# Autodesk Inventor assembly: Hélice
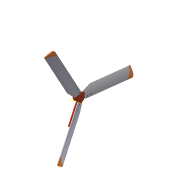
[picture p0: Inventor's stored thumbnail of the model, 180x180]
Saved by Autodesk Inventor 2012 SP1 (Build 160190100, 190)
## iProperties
Created: 2012-06
Part Number: Hélice
Document SubType Name: Assembly
Designer: Bruno
Mass: 33.8441 g
Surface Area: 261.603 cm^2
Volume: 32.2428 cm^3
Density: 1.04967 g/cm^3
Author: Bruno
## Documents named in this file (4)
- D:\Cours\1-Cours-2012-13\My Box Files\1-ITEC\9-Cinématique-V=W.R-Ventilo\ventilo-2\Hélice.iam
- D:\Cours\1-Cours-2012-13\My Box Files\1-ITEC\9-Cinématique-V=W.R-Ventilo\ventilo-2\Axe-helice.ipt
- D:\Cours\1-Cours-2012-13\My Box Files\1-ITEC\9-Cinématique-V=W.R-Ventilo\ventilo-2\014 Pale2.ipt
- C:\Users\Bruno\Documents\Inventor\Content Center Files\R2012\fr-FR\JIS B 1111  H (2)\JIS B 1111 - A M2 x 8 - H(1).ipt
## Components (10 placed, 3 different names)
1. Axe-helice:1 — Placage:5, Placage:6, Placage:7, Placage:8, Placage:9, Placage:10, Placage:11, Placage:12, Placage:13
2. 014 Pale2:1 — Placage:7, Placage:8, Placage:12, Logement:20, Logement:21
3. 014 Pale2:2 — Placage:9, Placage:10, Placage:13, Logement:16, Logement:17
4. 014 Pale2:3 — Placage:5, Placage:6, Placage:11, Logement:18, Logement:19
5. JIS B 1111 H - Métrique A M2 x 8 - H:3 — Logement:16
6. JIS B 1111 H - Métrique A M2 x 8 - H:4 — Logement:20
7. JIS B 1111 H - Métrique A M2 x 8 - H:5 — Logement:19
8. JIS B 1111 H - Métrique A M2 x 8 - H:6 — Logement:18
9. JIS B 1111 H - Métrique A M2 x 8 - H:7 — Logement:17
10. JIS B 1111 H - Métrique A M2 x 8 - H:8 — Logement:21
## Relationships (15: Mate 9, Insert 6)
- Placage:5 [Mate]: Axe-helice:1 ↔ 014 Pale2:3
- Placage:6 [Mate]: Axe-helice:1 ↔ 014 Pale2:3
- Placage:7 [Mate]: Axe-helice:1 ↔ 014 Pale2:1
- Placage:8 [Mate]: Axe-helice:1 ↔ 014 Pale2:1
- Placage:9 [Mate]: Axe-helice:1 ↔ 014 Pale2:2
- Placage:10 [Mate]: Axe-helice:1 ↔ 014 Pale2:2
- Placage:11 [Mate]: Axe-helice:1 ↔ 014 Pale2:3
- Placage:12 [Mate]: Axe-helice:1 ↔ 014 Pale2:1
- Placage:13 [Mate]: Axe-helice:1 ↔ 014 Pale2:2
- Logement:16 [Insert]: 014 Pale2:2 ↔ JIS B 1111 H - Métrique A M2 x 8 - H:3
- Logement:17 [Insert]: 014 Pale2:2 ↔ JIS B 1111 H - Métrique A M2 x 8 - H:7
- Logement:18 [Insert]: 014 Pale2:3 ↔ JIS B 1111 H - Métrique A M2 x 8 - H:6
- Logement:19 [Insert]: 014 Pale2:3 ↔ JIS B 1111 H - Métrique A M2 x 8 - H:5
- Logement:20 [Insert]: 014 Pale2:1 ↔ JIS B 1111 H - Métrique A M2 x 8 - H:4
- Logement:21 [Insert]: 014 Pale2:1 ↔ JIS B 1111 H - Métrique A M2 x 8 - H:8
